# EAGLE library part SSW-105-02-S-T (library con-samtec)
THROUGH-HOLE .025" SQ POST SOCKET Source: Samtec SSW.pdf
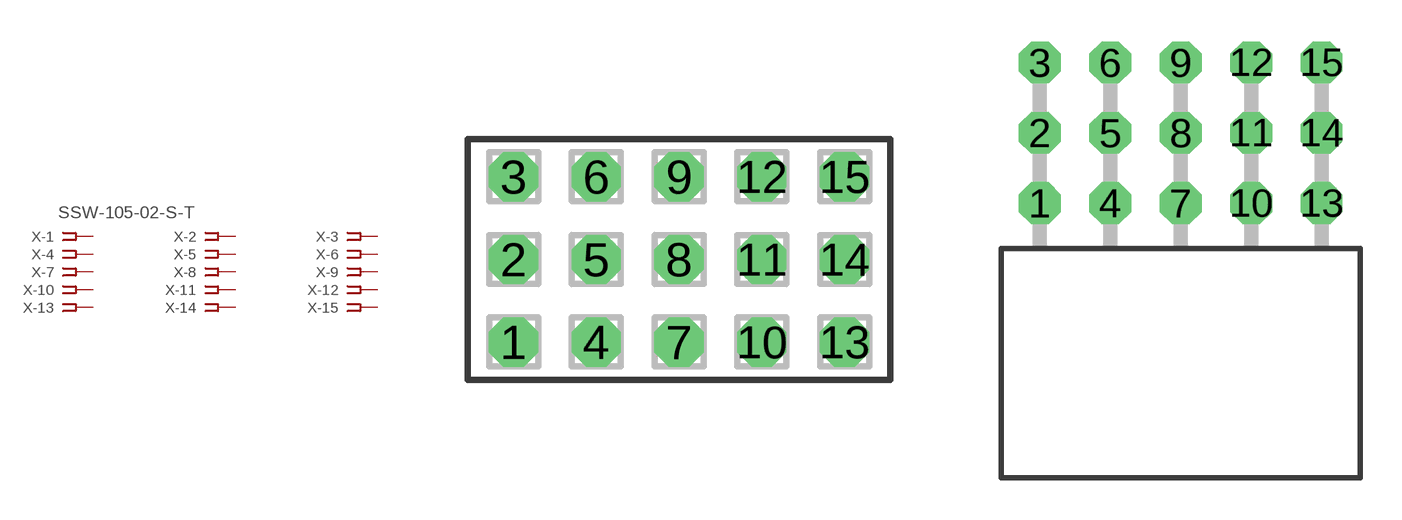
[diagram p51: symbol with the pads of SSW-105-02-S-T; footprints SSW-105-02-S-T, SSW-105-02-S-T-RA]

Designator prefix X; gates -1=FPINV -2=FPIN -3=FPIN -4=FPIN -5=FPIN -6=FPIN -7=FPIN -8=FPIN -9=FPIN -10=FPIN -11=FPIN -12=FPIN -13=FPIN -14=FPIN -15=FPIN

## SSW-105-02-S-T (MPN: SSW-105-02-S-T; OC_FARNELL: unknown; OC_NEWARK: 82P2934)  [SSW-105-02-S-T]
1  -1:1  pas
2  -2:1  pas
3  -3:1  pas
4  -4:1  pas
5  -5:1  pas
6  -6:1  pas
7  -7:1  pas
8  -8:1  pas
9  -9:1  pas
10  -10:1  pas
11  -11:1  pas
12  -12:1  pas
13  -13:1  pas
14  -14:1  pas
15  -15:1  pas

## SSW-105-02-S-TRA (MPN: SSW-105-02-S-T-RA; OC_FARNELL: unknown; OC_NEWARK: 82P2935)  [SSW-105-02-S-T-RA]
Pads as for SSW-105-02-S-T

## Footprint SSW-105-02-S-T (pad centres in mm)
THROUGH-HOLE .025" SQ POST SOCKET Source: Samtec SSW.pdf
drill 1 pad 1.5 octagon: 1 -5.08,-2.54; 2 -5.08,0; 3 -5.08,2.54; 4 -2.54,-2.54; 5 -2.54,0; 6 -2.54,2.54; 7 0,-2.54; 8 0,0; 9 0,2.54; 10 2.54,-2.54; 11 2.54,0; 12 2.54,2.54; 13 5.08,-2.54; 14 5.08,0; 15 5.08,2.54

## Footprint SSW-105-02-S-T-RA (pad centres in mm)
THROUGH-HOLE .025" SQ POST SOCKET Source: Samtec SSW.pdf
drill 1 pad 1.5 octagon: 1 -5.08,1.524; 2 -5.08,4.064; 3 -5.08,6.604; 4 -2.54,1.524; 5 -2.54,4.064; 6 -2.54,6.604; 7 0,1.524; 8 0,4.064; 9 0,6.604; 10 2.54,1.524; 11 2.54,4.064; 12 2.54,6.604; 13 5.08,1.524; 14 5.08,4.064; 15 5.08,6.604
